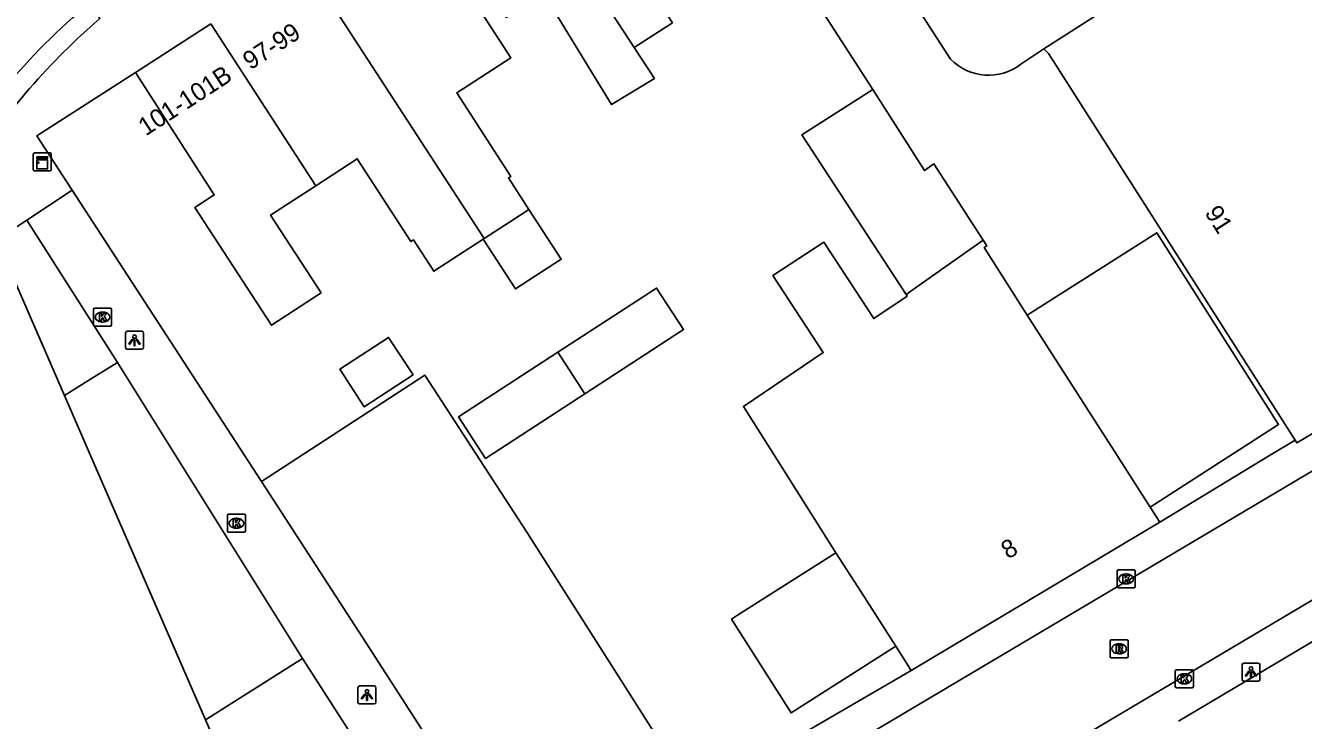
# Model space of a CAD drawing. Extents: x 159503 to 160347, y 382525 to 383272.
# Drawn here: x 159552.9 to 159623.7, y 382985.3 to 383023.8 of the extents above; entities that cross this region are included whole.
import ezdxf

# ---------------------------------------------------------------- set-up
doc = ezdxf.new("R2010")
doc.units = 0
for name, color, linetype in [('IMGEO_Fietspad_gesloten', 7, 'Continuous'), ('IMGEO_Hek', 7, 'Continuous'), ('IMGEO_Kast', 7, 'Continuous'), ('IMGEO_Kolk', 7, 'Continuous'), ('IMGEO_Lichtpunt', 7, 'Continuous'), ('IMGEO_Muur', 7, 'Continuous'), ('IMGEO_Pand', 7, 'Continuous'), ('IMGEO_Pand_nummerreeks', 7, 'Continuous'), ('IMGEO_Pand_overbouw', 7, 'Continuous'), ('IMGEO_Parkeervlak_open', 7, 'Continuous'), ('IMGEO_Rijbaan_lokaal_open', 7, 'Continuous'), ('IMGEO_Rioolput', 7, 'Continuous'), ('IMGEO_Voetpad_open', 7, 'Continuous')]:
    doc.layers.add(name, color=color, linetype=linetype)

msp = doc.modelspace()

# ---------------------------------------------------------------- linework, layer by layer
at = {"layer": 'IMGEO_Fietspad_gesloten'}
msp.add_arc((159577.671, 382999.148), 33.473, 129.33739, 140.71147, dxfattribs=at)
at = {"layer": 'IMGEO_Hek'}
for points in [[(159558.003, 383005.149), (159556.515, 383004.226)], [(159558.003, 383005.149), (159568.247, 382988.759)], [(159556.515, 383004.226), (159555.064, 383003.326)], [(159568.247, 382988.759), (159566.99, 382987.966)], [(159566.99, 382987.966), (159562.875, 382985.371)]]:
    msp.add_lwpolyline(points, dxfattribs=at)
at = {"layer": 'IMGEO_Kast'}
for p, q in [((159553.334, 383015.832), (159553.334, 383016.673)), ((159553.334, 383016.673), (159553.334, 383015.832)), ((159553.409, 383016.757), (159554.25, 383016.757)), ((159554.25, 383016.757), (159553.409, 383016.757)), ((159554.334, 383016.682), (159554.334, 383015.841)), ((159554.334, 383015.841), (159554.334, 383016.682)), ((159554.259, 383015.757), (159553.418, 383015.757)), ((159553.418, 383015.757), (159554.259, 383015.757))]:
    msp.add_line(p, q, dxfattribs=at)
for points in [[(159553.529, 383016.547), (159554.129, 383016.547), (159554.129, 383016.462), (159553.529, 383016.462), (159553.529, 383016.547)], [(159553.529, 383016.372), (159554.129, 383016.372), (159554.129, 383015.883), (159553.529, 383015.883), (159553.529, 383016.372)]]:
    msp.add_lwpolyline(points, dxfattribs=at)
msp.add_circle((159553.613, 383016.221), 0.0377, dxfattribs=at)
for centre, start, end in [((159553.412, 383016.679), 92.4484, 184.28452), ((159553.412, 383016.679), 92.4484, 184.28452), ((159554.256, 383016.679), 2.4484, 94.28452), ((159554.256, 383016.679), 2.4484, 94.28452), ((159553.412, 383015.835), 182.4484, 274.28452), ((159553.412, 383015.835), 182.4484, 274.28452), ((159554.256, 383015.835), 272.4484, 4.28452), ((159554.256, 383015.835), 272.4484, 4.28452)]:
    msp.add_arc(centre, 0.0779, start, end, dxfattribs=at)
at = {"layer": 'IMGEO_Kolk'}
for p, q in [((159556.677, 383007.24), (159556.677, 383008.092)), ((159556.752, 383008.166), (159557.604, 383008.166)), ((159557.678, 383008.092), (159557.678, 383007.24)), ((159557.188, 383007.386), (159557.163, 383007.386)), ((159557.165, 383007.946), (159557.19, 383007.946)), ((159557.604, 383007.166), (159556.752, 383007.166)), ((159564.164, 382996.75), (159565.016, 382996.75)), ((159564.089, 382995.824), (159564.089, 382996.676)), ((159564.577, 382996.53), (159564.602, 382996.53)), ((159565.09, 382996.676), (159565.09, 382995.824)), ((159565.016, 382995.75), (159564.164, 382995.75)), ((159564.6, 382995.97), (159564.575, 382995.97)), ((159613.361, 382992.743), (159613.361, 382993.595)), ((159613.436, 382993.669), (159614.288, 382993.669)), ((159613.849, 382993.449), (159613.874, 382993.449)), ((159614.362, 382993.595), (159614.362, 382992.743)), ((159614.288, 382992.669), (159613.436, 382992.669)), ((159613.872, 382992.889), (159613.847, 382992.889)), ((159616.587, 382987.212), (159616.587, 382988.064)), ((159616.662, 382988.138), (159617.514, 382988.138)), ((159617.075, 382987.918), (159617.1, 382987.918)), ((159617.588, 382988.064), (159617.588, 382987.212)), ((159617.514, 382987.138), (159616.662, 382987.138)), ((159617.098, 382987.358), (159617.073, 382987.358))]:
    msp.add_line(p, q, dxfattribs=at)
for points in [[(159556.677, 383007.24), (159556.677, 383008.092)], [(159556.752, 383008.166), (159557.604, 383008.166)], [(159557.678, 383008.092), (159557.678, 383007.24)], [(159556.998, 383007.866), (159557.121, 383007.866), (159557.121, 383007.715), (159557.251, 383007.866), (159557.415, 383007.866), (159557.269, 383007.715), (159557.422, 383007.466), (159557.27, 383007.466), (159557.185, 383007.63), (159557.121, 383007.563), (159557.121, 383007.466), (159556.998, 383007.466), (159556.998, 383007.866)], [(159557.604, 383007.166), (159556.752, 383007.166)], [(159564.164, 382996.75), (159565.016, 382996.75)], [(159564.089, 382995.824), (159564.089, 382996.676)], [(159564.41, 382996.45), (159564.533, 382996.45), (159564.533, 382996.299), (159564.663, 382996.45), (159564.827, 382996.45), (159564.681, 382996.299), (159564.834, 382996.05), (159564.682, 382996.05), (159564.597, 382996.214), (159564.533, 382996.147), (159564.533, 382996.05), (159564.41, 382996.05), (159564.41, 382996.45)], [(159565.09, 382996.676), (159565.09, 382995.824)], [(159565.016, 382995.75), (159564.164, 382995.75)], [(159613.361, 382992.743), (159613.361, 382993.595)], [(159613.436, 382993.669), (159614.288, 382993.669)], [(159613.682, 382993.369), (159613.805, 382993.369), (159613.805, 382993.218), (159613.935, 382993.369), (159614.099, 382993.369), (159613.953, 382993.218), (159614.106, 382992.969), (159613.954, 382992.969), (159613.869, 382993.133), (159613.805, 382993.066), (159613.805, 382992.969), (159613.682, 382992.969), (159613.682, 382993.369)], [(159614.362, 382993.595), (159614.362, 382992.743)], [(159614.288, 382992.669), (159613.436, 382992.669)], [(159616.587, 382987.212), (159616.587, 382988.064)], [(159616.662, 382988.138), (159617.514, 382988.138)], [(159616.908, 382987.838), (159617.031, 382987.838), (159617.031, 382987.687), (159617.161, 382987.838), (159617.325, 382987.838), (159617.179, 382987.687), (159617.332, 382987.438), (159617.18, 382987.438), (159617.095, 382987.602), (159617.031, 382987.535), (159617.031, 382987.438), (159616.908, 382987.438), (159616.908, 382987.838)], [(159617.588, 382988.064), (159617.588, 382987.212)], [(159617.514, 382987.138), (159616.662, 382987.138)]]:
    msp.add_lwpolyline(points, dxfattribs=at)
for centre, start, end in [((159556.754, 383008.09), 91.55205, 178.44795), ((159556.754, 383008.09), 91.55205, 178.44795), ((159557.602, 383008.09), 1.55205, 88.44795), ((159557.602, 383008.09), 1.55205, 88.44795), ((159556.754, 383007.242), 181.55205, 268.44795), ((159556.754, 383007.242), 181.55205, 268.44795), ((159557.602, 383007.242), 271.55205, 358.44795), ((159557.602, 383007.242), 271.55205, 358.44795), ((159564.166, 382996.674), 91.55205, 178.44795), ((159564.166, 382996.674), 91.55205, 178.44795), ((159565.014, 382996.674), 1.55205, 88.44795), ((159565.014, 382996.674), 1.55205, 88.44795), ((159564.166, 382995.826), 181.55205, 268.44795), ((159564.166, 382995.826), 181.55205, 268.44795), ((159565.014, 382995.826), 271.55205, 358.44795), ((159565.014, 382995.826), 271.55205, 358.44795), ((159613.438, 382993.593), 91.55205, 178.44795), ((159613.438, 382993.593), 91.55205, 178.44795), ((159614.286, 382993.593), 1.55205, 88.44795), ((159614.286, 382993.593), 1.55205, 88.44795), ((159613.438, 382992.745), 181.55205, 268.44795), ((159613.438, 382992.745), 181.55205, 268.44795), ((159614.286, 382992.745), 271.55205, 358.44795), ((159614.286, 382992.745), 271.55205, 358.44795), ((159616.664, 382988.062), 91.55205, 178.44795), ((159616.664, 382988.062), 91.55205, 178.44795), ((159617.512, 382988.062), 1.55205, 88.44795), ((159617.512, 382988.062), 1.55205, 88.44795), ((159616.664, 382987.214), 181.55205, 268.44795), ((159616.664, 382987.214), 181.55205, 268.44795), ((159617.512, 382987.214), 271.55205, 358.44795), ((159617.512, 382987.214), 271.55205, 358.44795)]:
    msp.add_arc(centre, 0.0765, start, end, dxfattribs=at)
for centre, major_axis, ratio, start_param, end_param in [((159557.164, 383007.666), (-0.387, 0.002), 0.722429, 4.712389, 7.853982), ((159557.189, 383007.666), (-0.39, 0.002), 0.717154, 1.570796, 4.712389), ((159564.576, 382996.25), (-0.387, 0.002), 0.722429, 4.712389, 7.853982), ((159564.601, 382996.25), (-0.39, 0.002), 0.717154, 1.570796, 4.712389), ((159613.848, 382993.169), (-0.387, 0.002), 0.722429, 4.712389, 7.853982), ((159613.873, 382993.169), (-0.39, 0.002), 0.717154, 1.570796, 4.712389), ((159617.074, 382987.638), (-0.387, 0.002), 0.722429, 4.712389, 7.853982), ((159617.099, 382987.638), (-0.39, 0.002), 0.717154, 1.570796, 4.712389)]:
    msp.add_ellipse(centre, major_axis=major_axis, ratio=ratio, start_param=start_param, end_param=end_param, dxfattribs=at)
at = {"layer": 'IMGEO_Lichtpunt'}
for p, q in [((159558.448, 383006.783), (159558.448, 383005.976)), ((159558.448, 383006.783), (159558.448, 383005.976)), ((159559.35, 383006.878), (159558.542, 383006.878)), ((159559.35, 383006.878), (159558.542, 383006.878)), ((159559.444, 383005.976), (159559.444, 383006.783)), ((159559.444, 383005.976), (159559.444, 383006.783)), ((159558.542, 383005.882), (159559.35, 383005.882)), ((159558.542, 383005.882), (159559.35, 383005.882)), ((159620.281, 382988.409), (159620.281, 382987.602)), ((159620.281, 382988.409), (159620.281, 382987.602)), ((159621.183, 382988.504), (159620.375, 382988.504)), ((159621.183, 382988.504), (159620.375, 382988.504)), ((159621.277, 382987.602), (159621.277, 382988.409)), ((159621.277, 382987.602), (159621.277, 382988.409)), ((159571.319, 382987.147), (159571.319, 382986.34)), ((159571.319, 382987.147), (159571.319, 382986.34)), ((159572.221, 382987.242), (159571.413, 382987.242)), ((159572.221, 382987.242), (159571.413, 382987.242)), ((159572.315, 382986.34), (159572.315, 382987.147)), ((159572.315, 382986.34), (159572.315, 382987.147)), ((159620.375, 382987.508), (159621.183, 382987.508)), ((159620.375, 382987.508), (159621.183, 382987.508)), ((159571.413, 382986.246), (159572.221, 382986.246)), ((159571.413, 382986.246), (159572.221, 382986.246))]:
    msp.add_line(p, q, dxfattribs=at)
for points in [[(159558.822, 383006.447), (159558.861, 383006.419), (159558.673, 383006.157), (159558.635, 383006.184), (159558.822, 383006.447)], [(159558.924, 383006.399), (159558.971, 383006.399), (159558.971, 383006.077), (159558.924, 383006.077), (159558.924, 383006.399)], [(159559.034, 383006.419), (159559.072, 383006.446), (159559.259, 383006.184), (159559.22, 383006.156), (159559.034, 383006.419)], [(159620.655, 382988.073), (159620.694, 382988.045), (159620.506, 382987.783), (159620.468, 382987.81), (159620.655, 382988.073)], [(159620.757, 382988.025), (159620.804, 382988.025), (159620.804, 382987.703), (159620.757, 382987.703), (159620.757, 382988.025)], [(159620.867, 382988.045), (159620.905, 382988.072), (159621.092, 382987.81), (159621.053, 382987.782), (159620.867, 382988.045)], [(159571.693, 382986.811), (159571.732, 382986.783), (159571.544, 382986.521), (159571.506, 382986.548), (159571.693, 382986.811)], [(159571.795, 382986.763), (159571.842, 382986.763), (159571.842, 382986.441), (159571.795, 382986.441), (159571.795, 382986.763)], [(159571.905, 382986.783), (159571.943, 382986.81), (159572.13, 382986.548), (159572.091, 382986.52), (159571.905, 382986.783)]]:
    msp.add_lwpolyline(points, dxfattribs=at)
for centre in [(159558.947, 383006.581), (159620.78, 382988.207), (159571.818, 382986.945)]:
    msp.add_circle(centre, 0.0994, dxfattribs=at)
for centre, start, end in [((159558.542, 383006.783), 90, 180), ((159558.542, 383006.783), 90, 180), ((159559.35, 383006.783), 0, 90), ((159559.35, 383006.783), 0, 90), ((159558.542, 383005.976), 180, 270), ((159558.542, 383005.976), 180, 270), ((159559.35, 383005.976), 270, 0), ((159559.35, 383005.976), 270, 360), ((159620.375, 382988.409), 90, 180), ((159620.375, 382988.409), 90, 180), ((159621.183, 382988.409), 0, 90), ((159621.183, 382988.409), 0, 90), ((159620.375, 382987.602), 180, 270), ((159620.375, 382987.602), 180, 270), ((159621.183, 382987.602), 270, 0), ((159621.183, 382987.602), 270, 360), ((159571.413, 382987.147), 90, 180), ((159571.413, 382987.147), 90, 180), ((159572.221, 382987.147), 0, 90), ((159572.221, 382987.147), 0, 90), ((159571.413, 382986.34), 180, 270), ((159571.413, 382986.34), 180, 270), ((159572.221, 382986.34), 270, 0), ((159572.221, 382986.34), 270, 360)]:
    msp.add_arc(centre, 0.0946, start, end, dxfattribs=at)
at = {"layer": 'IMGEO_Muur'}
msp.add_lwpolyline([(159553.53, 383017.705), (159565.97, 382998.562)], dxfattribs=at)
at = {"layer": 'IMGEO_Pand'}
for points in [[(159579.027, 383034.22), (159586.617, 383022.585)], [(159586.617, 383022.585), (159587.738, 383020.879), (159585.363, 383019.431), (159584.722, 383020.483), (159584.461, 383020.911), (159581.635, 383025.545), (159579.532, 383024.263), (159574.845, 383031.499)], [(159580.786, 383013.624), (159579.654, 383015.369), (159579.789, 383015.457), (159576.79, 383020.079), (159579.787, 383022.025), (159574.012, 383030.96)], [(159635.355, 383008.004), (159621.4, 383030.261), (159609.307, 383022.512)], [(159586.617, 383022.585), (159588.736, 383023.968), (159585.936, 383028.26), (159588.098, 383029.67)], [(159578.308, 383012.015), (159568.383, 383027.302)], [(159558.995, 383021.203), (159563.163, 383023.911)], [(159563.163, 383023.911), (159568.983, 383014.938)], [(159609.307, 383022.512), (159609.564, 383022.268), (159623.224, 383000.858)], [(159558.995, 383021.203), (159563.358, 383014.434), (159562.293, 383013.743), (159566.529, 383007.217), (159569.281, 383009.003), (159566.483, 383013.315), (159568.983, 383014.938)], [(159601.675, 383008.92), (159595.895, 383017.764), (159599.831, 383020.269)], [(159605.954, 383011.924), (159603.216, 383016.145), (159602.688, 383015.78), (159599.831, 383020.269)], [(159568.983, 383014.938), (159571.282, 383016.431), (159574.255, 383011.852), (159574.39, 383011.94), (159575.518, 383010.204), (159578.251, 383011.978)], [(159578.251, 383011.978), (159580.04, 383009.222), (159582.575, 383010.866), (159580.786, 383013.624)], [(159580.786, 383013.624), (159579.712, 383012.927), (159578.308, 383012.015)], [(159555.064, 383003.326), (159551.308, 383011.943)], [(159578.251, 383011.978), (159578.308, 383012.015)], [(159601.675, 383008.92), (159601.733, 383008.832), (159599.882, 383007.585), (159597.122, 383011.809), (159594.302, 383009.967), (159597.088, 383005.704), (159592.664, 383002.724), (159594.396, 383000), (159597.778, 382994.61)], [(159605.954, 383011.924), (159602.516, 383009.51), (159601.675, 383008.92)], [(159615.727, 382996.312), (159615.2, 382997.141), (159613.368, 383000), (159608.385, 383007.779), (159605.996, 383011.511), (159606.155, 383011.614), (159605.954, 383011.924)], [(159583.89, 383003.418), (159589.358, 383006.971), (159587.861, 383009.273), (159582.395, 383005.72)], [(159623.224, 383000.858), (159623.323, 383000.702), (159635.177, 383007.713), (159635.443, 383007.863), (159635.355, 383008.004)], [(159574.372, 383004.462), (159573.02, 383006.542), (159570.307, 383004.779), (159571.659, 383002.699), (159574.372, 383004.462)], [(159582.395, 383005.72), (159576.893, 383002.145), (159578.389, 382999.843), (159583.89, 383003.418)], [(159582.395, 383005.72), (159583.89, 383003.418)], [(159589.699, 382981.552), (159587.016, 382985.773), (159580.673, 382995.756), (159575.025, 383004.447), (159565.97, 382998.562)], [(159562.875, 382985.371), (159556.514, 383000), (159555.064, 383003.326)], [(159584.314, 382978.537), (159580.736, 382976.534), (159580.891, 382976.254), (159580.524, 382976.049), (159571.589, 382989.915), (159565.97, 382998.562)], [(159601.959, 382988.106), (159615.727, 382996.312)], [(159597.778, 382994.61), (159592.342, 382991.154), (159592.008, 382990.942), (159595.31, 382985.753), (159601.102, 382989.453)], [(159597.778, 382994.61), (159599.215, 382992.42), (159601.102, 382989.453)], [(159616.76, 382985.295), (159632.4, 382994.581)], [(159601.102, 382989.453), (159601.959, 382988.106)], [(159565.208, 382980.005), (159562.875, 382985.371)]]:
    msp.add_lwpolyline(points, dxfattribs=at)
at = {"layer": 'IMGEO_Pand_overbouw'}
msp.add_lwpolyline([(159615.2, 382997.141), (159622.309, 383001.721), (159615.563, 383012.339), (159608.385, 383007.779), (159613.368, 383000)], close=True, dxfattribs=at)
at = {"layer": 'IMGEO_Parkeervlak_open'}
msp.add_lwpolyline([(159568.247, 382988.759), (159566.99, 382987.966), (159562.875, 382985.371)], dxfattribs=at)
at = {"layer": 'IMGEO_Rijbaan_lokaal_open'}
for points in [[(159724.205, 383058.665), (159687.242, 383036.582), (159585.591, 382976.257)], [(159719.236, 383048.422), (159586.71, 382969.778)], [(159596.147, 383034.355), (159604.136, 383021.944)], [(159599.831, 383020.269), (159593.507, 383030.078)], [(159608.037, 383021.672), (159609.307, 383022.512)], [(159623.224, 383000.858), (159621.809, 383000), (159615.727, 382996.312)]]:
    msp.add_lwpolyline(points, dxfattribs=at)
msp.add_arc((159606.24, 383024.005), 2.945, 224.40823, 307.6147, dxfattribs=at)
at = {"layer": 'IMGEO_Rioolput'}
for p, q in [((159612.972, 382988.874), (159612.972, 382989.726)), ((159613.047, 382989.8), (159613.899, 382989.8)), ((159613.973, 382989.726), (159613.973, 382988.874)), ((159613.483, 382989.02), (159613.458, 382989.02)), ((159613.46, 382989.58), (159613.485, 382989.58)), ((159613.899, 382988.8), (159613.047, 382988.8))]:
    msp.add_line(p, q, dxfattribs=at)
for points in [[(159612.972, 382988.874), (159612.972, 382989.726)], [(159613.047, 382989.8), (159613.899, 382989.8)], [(159613.973, 382989.726), (159613.973, 382988.874)], [(159613.561, 382989.498), (159613.309, 382989.5), (159613.309, 382989.1)], [(159613.309, 382989.1), (159613.433, 382989.1), (159613.433, 382989.262), (159613.444, 382989.262)], [(159613.487, 382989.419), (159613.433, 382989.419), (159613.433, 382989.338)], [(159613.433, 382989.338), (159613.485, 382989.338)], [(159613.491, 382989.233), (159613.562, 382989.1), (159613.702, 382989.1), (159613.637, 382989.226)], [(159613.899, 382988.8), (159613.047, 382988.8)]]:
    msp.add_lwpolyline(points, dxfattribs=at)
for centre, radius, start, end in [((159613.049, 382989.724), 0.0765, 91.55205, 178.44795), ((159613.049, 382989.724), 0.0765, 91.55205, 178.44795), ((159613.897, 382989.724), 0.0765, 1.55205, 88.44795), ((159613.897, 382989.724), 0.0765, 1.55205, 88.44795), ((159613.443, 382989.209), 0.0533, 26.02933, 88.69889), ((159613.469, 382989.527), 0.19, 274.7715, 282.96867), ((159613.493, 382989.323), 0.0964, 77.00612, 93.18647), ((159613.507, 382989.38), 0.0378, 276.66336, 79.67722), ((159613.56, 382989.388), 0.109, 350.36119, 89.41601), ((159613.558, 382989.388), 0.112, 277.58423, 350.98172), ((159613.542, 382989.173), 0.108, 29.51342, 73.79051), ((159613.049, 382988.876), 0.0765, 181.55205, 268.44795), ((159613.049, 382988.876), 0.0765, 181.55205, 268.44795), ((159613.897, 382988.876), 0.0765, 271.55205, 358.44795), ((159613.897, 382988.876), 0.0765, 271.55205, 358.44795)]:
    msp.add_arc(centre, radius, start, end, dxfattribs=at)
for centre, major_axis, ratio, start_param, end_param in [((159613.459, 382989.3), (-0.387, 0.002), 0.722429, 4.712389, 7.853982), ((159613.484, 382989.3), (-0.39, 0.002), 0.717154, 1.570796, 4.712389)]:
    msp.add_ellipse(centre, major_axis=major_axis, ratio=ratio, start_param=start_param, end_param=end_param, dxfattribs=at)
at = {"layer": 'IMGEO_Voetpad_open'}
for points in [[(159555.783, 383023.083), (159557.017, 383024.193), (159556.453, 383025.037)], [(159555.492, 383014.686), (159553.53, 383017.705), (159558.995, 383021.203)], [(159555.492, 383014.686), (159552.985, 383013.033)], [(159565.97, 382998.562), (159555.492, 383014.686)], [(159551.308, 383011.943), (159552.985, 383013.033)], [(159552.985, 383013.033), (159558.003, 383005.149)], [(159558.003, 383005.149), (159556.515, 383004.226), (159555.064, 383003.326)], [(159558.003, 383005.149), (159568.247, 382988.759)], [(159568.247, 382988.759), (159572.27, 382982.509), (159570.807, 382982.041), (159567.995, 382981.142), (159565.208, 382980.005)], [(159589.699, 382981.552), (159589.966, 382981.122), (159601.638, 382987.915), (159601.959, 382988.106)]]:
    msp.add_lwpolyline(points, dxfattribs=at)
msp.add_arc((159583.513, 382993.821), 40.314, 133.46094, 141.36618, dxfattribs=at)

# ---------------------------------------------------------------- texts
at = {"layer": 'IMGEO_Pand_nummerreeks'}
for s, rotation, p in [('97-99', 32.97945, (159565.362, 383021.324)), ('101-101B', 33.01332, (159559.574, 383017.668)), ('91', 302.53767, (159618.184, 383013.442)), ('8', 30.79648, (159607.32, 382994.235))]:
    msp.add_text(s, height=1, rotation=rotation, dxfattribs=at).set_placement(p)

doc.saveas('drawing.dxf')
